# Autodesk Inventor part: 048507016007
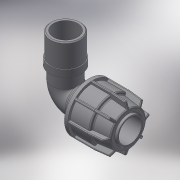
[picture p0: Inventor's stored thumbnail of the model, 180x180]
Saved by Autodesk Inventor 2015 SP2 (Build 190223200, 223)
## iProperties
Created: 2017-08
Part Number: 048507016007
Material: Generic
Description: PLASSON IRRIFIT ELBOW 16-3/4"M
Document SubType Name: Modeling
Designer: KIM
Density: 1 g/cm^3
Appearance: Default
Author: KIM
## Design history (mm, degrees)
derived "048507.ipt"
feature "Solid1::048507.ipt"
tag "TaggingFeature1"
body "Solid1"
other parameters: "d5" = 28.8, "d6" = 12.8, "d10" = 34, "d22" = 22.4, "d24" = 2.4, "d25" = 30.6, "d26" = 27.2, "d31" = 0.8, "d49" = 1.7, "d50" = 0, "d58" = 0.48, "d61" = 360 deg, "d77" = 16, "d78" = 6 deg, "d80" = 17.6, "d81" = 45, "d82" = 2.4, "d84" = 5 deg, "d85" = 70 deg, "d86" = 32.3, "d87" = 0.48, "d88" = 0, "d100" = 27.2, "d101" = 8, "d102" = 0, "d103" = 26.441, "d104" = 27.76305, "d105" = 17, "d107" = 16, "d108" = 21.1528, "d109" = 18.7, "d110" = 21.1528, "d111" = 22.1, "d113" = 0.79323, "d120" = 9, "d121" = 9, "d122" = 39, "d123" = 21.1528, "d124" = 2.25, "d125" = 90 deg, "d_" = 16, "E_" = 34, "A_" = 45, "l_" = 16, "A_1" = 39, "l_2" = 17, "R_" = 26.441, "d99" = 22.4
